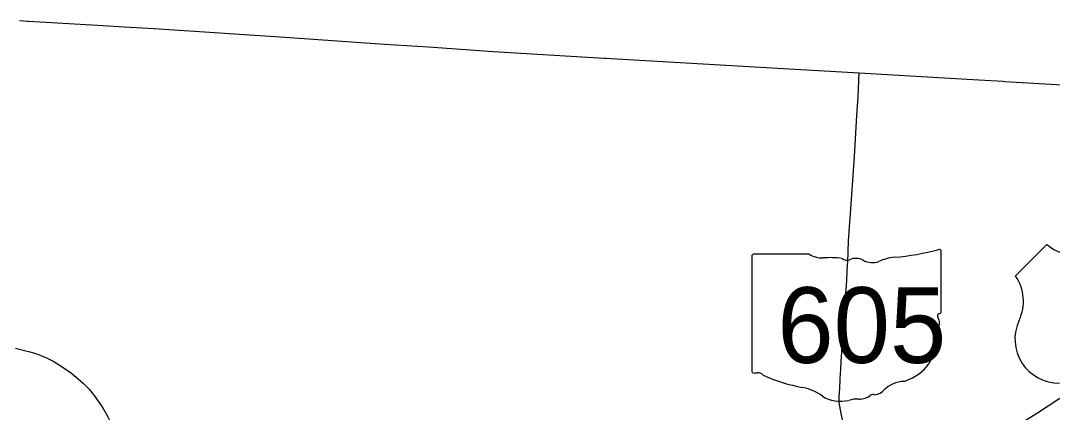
# Model space of a CAD drawing. Extents: x 0 to 34, y 0 to 22.
# Drawn here: x 6.732 to 8.488, y 19.363 to 20.029 of the extents above; entities that cross this region are included whole.
import ezdxf

# ---------------------------------------------------------------- set-up
doc = ezdxf.new("R2010")
doc.units = 0
for name, color, linetype in [('GM_X_County', 7, 'Continuous'), ('GM_X_Interstate_Route', 7, 'Continuous'), ('GM_X_State_Route', 7, 'Continuous'), ('GM_X_State_Shield', 7, 'Continuous'), ('GM_X_US_Route', 7, 'Continuous'), ('GM_X_US_Shield', 7, 'Continuous')]:
    doc.layers.add(name, color=color, linetype=linetype)

msp = doc.modelspace()

# ---------------------------------------------------------------- linework, layer by layer
at = {"layer": 'GM_X_County'}
msp.add_lwpolyline([(6.7299, 20.0295), (6.7433, 20.0287), (6.7449, 20.0286), (6.8721, 20.0214), (6.9077, 20.0191), (6.9587, 20.0161), (7.1896, 20.0007), (7.3512, 19.9896), (7.4256, 19.9846), (7.5359, 19.9771), (7.7247, 19.9658), (7.7271, 19.9657), (8.01, 19.9493), (8.1591, 19.9404), (8.3329, 19.9304), (8.3626, 19.9284), (8.4041, 19.9263), (8.4065, 19.9261), (8.5338, 19.9184)], dxfattribs=at)
at = {"layer": 'GM_X_Interstate_Route'}
for points in [[(6.7228, 19.4719), (6.7228, 19.4719), (6.7474, 19.4654), (6.7577, 19.4625), (6.7687, 19.4581), (6.7759, 19.4552), (6.7869, 19.4497), (6.7975, 19.4437), (6.8183, 19.4291)], [(6.8183, 19.4291), (6.8195, 19.4283), (6.8298, 19.4197), (6.8389, 19.4116), (6.8482, 19.4021), (6.8568, 19.3914), (6.8705, 19.3717), (6.8797, 19.3559), (6.8844, 19.3456), (6.8865, 19.341), (6.8894, 19.3341), (6.8916, 19.328), (6.8947, 19.3185), (6.8966, 19.3117), (6.8988, 19.303), (6.8995, 19.2998), (6.9007, 19.2933), (6.9024, 19.2841), (6.9034, 19.275), (6.9039, 19.2696), (6.9042, 19.2555)]]:
    msp.add_lwpolyline(points, dxfattribs=at)
at = {"layer": 'GM_X_State_Route'}
for points in [[(8.1393, 19.6179), (8.1409, 19.6547), (8.1429, 19.686), (8.1433, 19.6926), (8.1507, 19.7979), (8.1551, 19.8678), (8.1572, 19.9004), (8.1591, 19.9404)], [(8.1376, 19.5863), (8.1378, 19.5887), (8.1392, 19.614), (8.1393, 19.6179)], [(8.1278, 19.4363), (8.1284, 19.4492), (8.1295, 19.4656), (8.1343, 19.5381), (8.1356, 19.5573), (8.1376, 19.5863)], [(8.1266, 19.4199), (8.1278, 19.4363)], [(8.1253, 19.3964), (8.1257, 19.4037), (8.1266, 19.4193), (8.1266, 19.4199)], [(8.1446, 19.3152), (8.1413, 19.3212), (8.1384, 19.3269), (8.1351, 19.3342), (8.1333, 19.3392), (8.1325, 19.3419), (8.13, 19.352), (8.1292, 19.355), (8.1253, 19.376), (8.1249, 19.379), (8.1247, 19.3831), (8.1248, 19.3888), (8.1253, 19.3964)]]:
    msp.add_lwpolyline(points, dxfattribs=at)
at = {"layer": 'GM_X_State_Shield'}
for p, q in [((8.0738, 19.6318), (7.9795, 19.6318)), ((8.2984, 19.5344), (8.2984, 19.6367)), ((7.9763, 19.6285), (7.9763, 19.4329)), ((8.2984, 19.5344), (8.2984, 19.5344))]:
    msp.add_line(p, q, dxfattribs=at)
for centre, major_axis, start_param, end_param in [((7.98, 19.6289), (0.00373, 0), 1.712693, 3.28349), ((8.0963, 19.6545), (0.0362, 0), 4.042523, 4.731795), ((8.1837, 19.8985), (0.3416, 0), 4.814394, 5.042369), ((8.2948, 19.6371), (0.00359, 0), 6.141152, 7.989035), ((8.1083, 19.522), (0.1299, 0), 1.404758, 1.657858), ((8.1378, 19.6299), (0.0104, 0), 3.836095, 5.185415), ((8.1531, 19.6073), (0.0217, 0), 0.950623, 2.079405), ((8.1811, 19.6383), (0.0261, 0), 4.081561, 5.145723), ((8.2272, 19.5721), (0.0687, 0), 1.699011, 2.107814), ((8.2976, 19.5269), (0.00555, 0), 1.883978, 3.671073), ((8.2946, 19.534), (0.00384, 0), 5.05454, 6.418171), ((8.2623, 19.5139), (0.0333, 0), 5.934695, 6.695948), ((8.3113, 19.4916), (0.0242, 0), 2.387724, 3.262537), ((8.2028, 19.4785), (0.0854, 0), 5.101752, 6.440018), ((7.98, 19.4325), (0.00376, 0), 3.00124, 4.508301), ((7.9806, 19.4525), (0.0287, 0), 4.665946, 4.897461), ((7.9865, 19.4216), (0.0104, 0), 0.519207, 1.627899), ((8.1173, 19.5973), (0.2467, 0), 4.195997, 4.488961), ((8.0437, 19.345), (0.0772, 0), 0.823519, 1.323587), ((8.2388, 19.378), (0.0468, 0), 1.647645, 2.488434), ((8.1272, 19.4206), (0.049, 0), 4.026481, 4.996735), ((8.1591, 19.406), (0.0261, 0), 4.691044, 5.507374), ((8.1827, 19.387), (0.00735, 0), 1.147584, 2.315152), ((8.1795, 19.4139), (0.0276, 0), 4.937069, 5.64225), ((8.1555, 19.353), (0.0402, 0), 1.495662, 1.94098)]:
    msp.add_ellipse(centre, major_axis=major_axis, ratio=0.8, start_param=start_param, end_param=end_param, dxfattribs=at)
at = {"layer": 'GM_X_US_Route'}
msp.add_lwpolyline([(8.4252, 19.3391), (8.4384, 19.3469), (8.4621, 19.3619), (8.4987, 19.3853), (8.5087, 19.3916)], dxfattribs=at)
at = {"layer": 'GM_X_US_Shield'}
msp.add_line((8.4785, 19.6485), (8.4248, 19.5948), dxfattribs=at)
for centre, radius, start, end in [((8.5161, 19.6869), 0.0537, 225.573, 314.427), ((8.3632, 19.5517), 0.0752, 334.5471, 35.0009), ((8.4991, 19.4875), 0.0752, 154.8319, 270.6383)]:
    msp.add_arc(centre, radius, start, end, dxfattribs=at)

# ---------------------------------------------------------------- texts
at = {"layer": 'GM_X_State_Shield'}
msp.add_text('605', height=0.12885, dxfattribs=at).set_placement((8.0196, 19.4467))

doc.saveas('drawing.dxf')
